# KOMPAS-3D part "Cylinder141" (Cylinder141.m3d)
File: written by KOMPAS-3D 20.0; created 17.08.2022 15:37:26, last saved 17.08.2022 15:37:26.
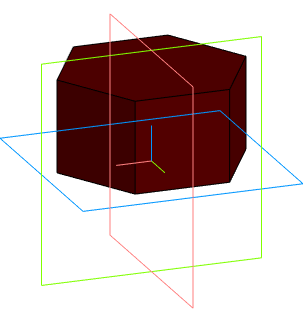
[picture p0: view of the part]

Document properties: Автор: artemsv220@gmail.com; Полное имя файла: \\192.168.2.25\новая общая папка\Медиа\Светильники\Кашпо\Кашпо и вазоны\DWG\Cylinder141.m3d

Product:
- Part/product: Cylinder141

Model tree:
1. Операция без истории:1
